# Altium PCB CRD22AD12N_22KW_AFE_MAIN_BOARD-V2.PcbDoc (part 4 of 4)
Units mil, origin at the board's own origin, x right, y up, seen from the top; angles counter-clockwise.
Board outline 14411 x 7330.3 mil, 4 copper layers (TOP, GND02, POWER03, BOTTOM), stack 78.531 mil thick; 589 components, 281 nets, 1401 pads, 282 vias.
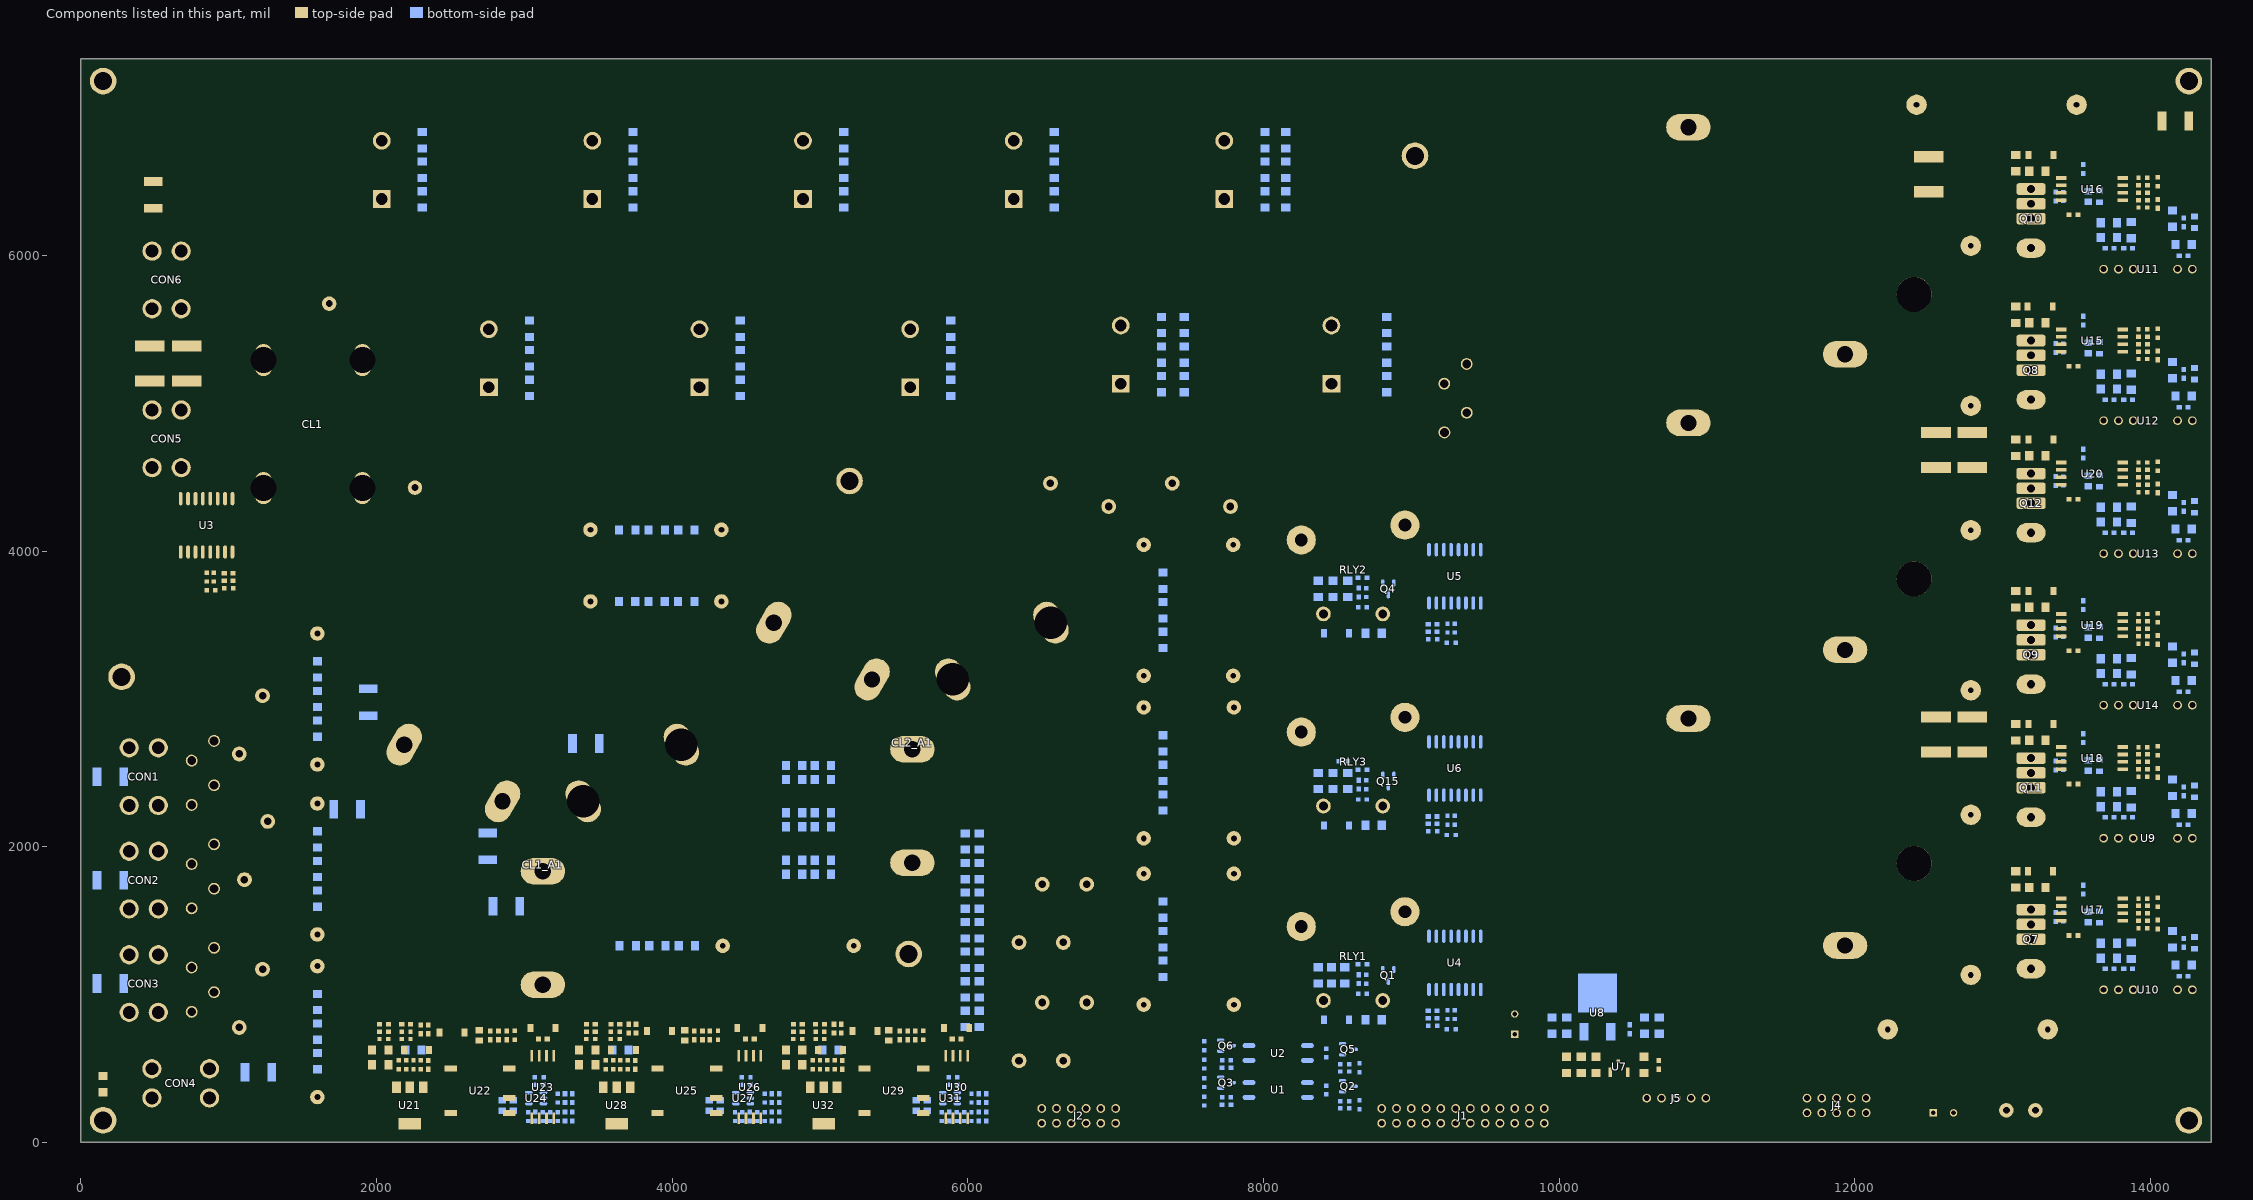
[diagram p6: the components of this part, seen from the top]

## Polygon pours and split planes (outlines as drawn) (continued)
N17916039 on POWER03 "POWER03-N17916039" (solid, pour order 101): 36 vertices, not listed, extent 9340,697.5 13460,7150

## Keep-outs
Multi-Layer:
  region: 13088.63,3180.31 13297.29,3180.31 13297.29,3219.68 13088.63,3219.68

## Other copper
TOP:
  pour cut-out: 1781.41,2300 ccw(c1950,2300) 1950,2131.41 ccw(c1950,2300) 2118.59,2300 ccw(c1950,2300) 1950,2468.59 ccw(c1950,2300)
  pour cut-out: 7061,2057.09 ccw(c7190,2057.09) 7190,1928.09 ccw(c7190,2057.09) 7319,2057.09 ccw(c7190,2057.09) 7190,2186.09 ccw(c7190,2057.09)
  pour cut-out: 5350,1275 ccw(c5600,1275) 5600,1025 ccw(c5600,1275) 5850,1275 ccw(c5600,1275) 5600,1525 ccw(c5600,1275)
  pour cut-out: 1391,2292.91 ccw(c1600,2292.91) 1600,2083.91 ccw(c1600,2292.91) 1809,2292.91 ccw(c1600,2292.91) 1600,2501.91 ccw(c1600,2292.91)
  pour cut-out: 1781.41,2200 ccw(c1950,2200) 1950,2031.41 ccw(c1950,2200) 2118.59,2200 ccw(c1950,2200) 1950,2368.59 ccw(c1950,2200)
  pour cut-out: 8775,6675 ccw(c9025,6675) 9025,6425 ccw(c9025,6675) 9275,6675 ccw(c9025,6675) 9025,6925 ccw(c9025,6675)
  pour cut-out: 4551.54,1330 4549.75,1357.34 4544.4,1384.21 4535.6,1410.15 4523.48,1434.73 4508.26,1457.51 4490.19,1478.1 4469.6,1496.17 4446.82,1511.39 4422.24,1523.51 4396.3,1532.31 4369.43,1537.66 4342.09,1539.45 4314.75,1537.66 4287.88,1532.31 4261.94,1523.51 4237.37,1511.39 4214.59,1496.17 4193.99,1478.1 4175.92,1457.51 4160.7,1434.73 4148.58,1410.15 4139.78,1384.21 4134.43,1357.34 4132.64,1330 4134.43,1302.66 4139.78,1275.79 4148.58,1249.85 4160.7,1225.27 4175.92,1202.49 4193.99,1181.9 4214.59,1163.83 4237.37,1148.61 4261.94,1136.49 4287.88,1127.69 4314.75,1122.34 4342.09,1120.55 4369.43,1122.34 4396.3,1127.69 4422.24,1136.49 4446.82,1148.61 4469.6,1163.83 4490.19,1181.9 4508.26,1202.49 4523.48,1225.27 4535.6,1249.85 4544.4,1275.79 4549.75,1302.66 4551.54,1330
  pour cut-out: 1779.48,1300 1788.13,1283.95 1795.35,1267.21 1801.08,1249.9 1805.28,1232.15 1807.92,1214.11 1808.98,1195.91 1809,1192.91 1808.21,1174.69 1805.83,1156.62 1801.88,1138.82 1796.4,1121.43 1789.42,1104.58 1781,1088.41 1771.2,1073.03 1760.1,1058.57 1747.79,1045.12 1734.34,1032.8 1719.88,1021.7 1704.5,1011.91 1688.33,1003.49 1671.48,996.51 1654.09,991.03 1636.29,987.08 1618.22,984.7 1600,983.91 1581.78,984.7 1563.71,987.08 1545.91,991.03 1528.52,996.51 1511.67,1003.49 1495.5,1011.91 1480.12,1021.7 1465.66,1032.8 1452.21,1045.12 1439.9,1058.57 1428.8,1073.03 1419,1088.41 1410.58,1104.58 1403.6,1121.43 1398.12,1138.82 1394.17,1156.62 1391.79,1174.69 1391,1192.91 1391.79,1211.12 1394.17,1229.2 1398.12,1247 1403.6,1264.39 1410.58,1281.24 1419,1297.41 1420.52,1300 1411.87,1316.05 1404.65,1332.79 1398.92,1350.1 1394.72,1367.84 1392.08,1385.88 1391.02,1404.09 1391,1407.09 1391.79,1425.3 1394.17,1443.38 1398.12,1461.18 1403.6,1478.57 1410.58,1495.42 1419,1511.59 1428.8,1526.97 1439.9,1541.43 1452.21,1554.88 1465.66,1567.19 1480.12,1578.29 1495.5,1588.09 1511.67,1596.51 1528.52,1603.49 1545.91,1608.97 1563.71,1612.92 1581.78,1615.3 1600,1616.09 1618.22,1615.3 1636.29,1612.92 1654.09,1608.97 1671.48,1603.49 1688.33,1596.51 1704.5,1588.09 1719.88,1578.29 1734.34,1567.19 1747.79,1554.88 1760.1,1541.43 1771.2,1526.97 1781,1511.59 1789.42,1495.42 1796.4,1478.57 1801.88,1461.18 1805.83,1443.38 1808.21,1425.3 1809,1407.09 1808.21,1388.87 1805.83,1370.8 1801.88,1353 1796.4,1335.61 1789.42,1318.76 1781,1302.59 1779.48,1300
  pour cut-out: 5700.48,1275 5698.55,1294.6 5692.84,1313.45 5683.55,1330.83 5671.05,1346.05 5655.83,1358.55 5638.45,1367.83 5619.6,1373.55 5600,1375.48 5580.4,1373.55 5561.54,1367.83 5549.97,1361.65 5544.17,1358.55 5528.94,1346.05 5516.45,1330.83 5507.16,1313.45 5501.44,1294.6 5499.51,1275 5501.44,1255.39 5507.16,1236.54 5516.45,1219.17 5528.94,1203.94 5544.17,1191.45 5549.97,1188.35 5561.54,1182.16 5580.4,1176.44 5600,1174.51 5619.6,1176.44 5638.45,1182.16 5655.83,1191.45 5671.05,1203.94 5683.55,1219.17 5692.84,1236.54 5698.55,1255.39 5700.48,1275
  pour cut-out: 14324.09,5908.07 14322.74,5918.38 14318.76,5927.99 14312.42,5936.24 14304.17,5942.57 14294.56,5946.55 14284.25,5947.91 14273.94,5946.55 14264.33,5942.57 14256.08,5936.24 14249.74,5927.99 14245.76,5918.38 14244.41,5908.07 14245.76,5897.76 14249.74,5888.15 14256.08,5879.9 14264.33,5873.56 14273.94,5869.58 14284.25,5868.23 14294.56,5869.58 14304.17,5873.56 14312.42,5879.9 14318.76,5888.15 14322.74,5897.76 14324.09,5908.07
  pour cut-out: 14324.09,4883.07 14322.74,4893.38 14318.76,4902.99 14312.42,4911.24 14304.17,4917.57 14294.56,4921.55 14284.25,4922.91 14273.94,4921.55 14264.33,4917.57 14256.08,4911.24 14249.74,4902.99 14245.76,4893.38 14244.41,4883.07 14245.76,4872.76 14249.74,4863.15 14256.08,4854.9 14264.33,4848.56 14273.94,4844.58 14284.25,4843.23 14294.56,4844.58 14304.17,4848.56 14312.42,4854.9 14318.76,4863.15 14322.74,4872.76 14324.09,4883.07
  pour cut-out: 14324.09,3983.07 14322.74,3993.38 14318.76,4002.99 14312.42,4011.24 14304.17,4017.57 14294.56,4021.55 14284.25,4022.91 14273.94,4021.55 14264.33,4017.57 14256.08,4011.24 14249.74,4002.99 14245.76,3993.38 14244.41,3983.07 14245.76,3972.76 14249.74,3963.15 14256.08,3954.9 14264.33,3948.56 14273.94,3944.58 14284.25,3943.23 14294.56,3944.58 14304.17,3948.56 14312.42,3954.9 14318.76,3963.15 14322.74,3972.76 14324.09,3983.07
  pour cut-out: 14324.09,2958.07 14322.74,2968.38 14318.76,2977.99 14312.42,2986.24 14304.17,2992.57 14294.56,2996.55 14284.25,2997.91 14273.94,2996.55 14264.33,2992.57 14256.08,2986.24 14249.74,2977.99 14245.76,2968.38 14244.41,2958.07 14245.76,2947.76 14249.74,2938.15 14256.08,2929.9 14264.33,2923.56 14273.94,2919.58 14284.25,2918.23 14294.56,2919.58 14304.17,2923.56 14312.42,2929.9 14318.76,2938.15 14322.74,2947.76 14324.09,2958.07
  pour cut-out: 14324.09,2058.07 14322.74,2068.38 14318.76,2077.99 14312.42,2086.24 14304.17,2092.57 14294.56,2096.55 14284.25,2097.91 14273.94,2096.55 14264.33,2092.57 14256.08,2086.24 14249.74,2077.99 14245.76,2068.38 14244.41,2058.07 14245.76,2047.76 14249.74,2038.15 14256.08,2029.9 14264.33,2023.56 14273.94,2019.58 14284.25,2018.23 14294.56,2019.58 14304.17,2023.56 14312.42,2029.9 14318.76,2038.15 14322.74,2047.76 14324.09,2058.07
  pour cut-out: 10632.95,300 10631.6,310.31 10627.62,319.92 10621.28,328.17 10613.03,334.5 10603.42,338.49 10593.11,339.84 10582.8,338.49 10573.19,334.5 10564.94,328.17 10558.6,319.92 10554.62,310.31 10553.27,300 10554.62,289.69 10558.6,280.08 10564.94,271.83 10573.19,265.5 10582.8,261.51 10593.11,260.16 10603.42,261.51 10613.03,265.5 10621.28,271.83 10627.62,280.08 10631.6,289.69 10632.95,300
  pour cut-out: 7249.29,2057.09 7248.15,2068.66 7244.77,2079.78 7239.3,2090.03 7231.92,2099.01 7222.94,2106.39 7212.69,2111.87 7201.57,2115.24 7190,2116.38 7178.43,2115.24 7167.31,2111.87 7160.48,2108.22 7157.06,2106.39 7148.08,2099.01 7140.7,2090.03 7135.23,2079.78 7131.85,2068.66 7130.71,2057.09 7131.85,2045.52 7135.23,2034.4 7140.7,2024.15 7148.08,2015.17 7157.06,2007.8 7160.48,2005.97 7167.31,2002.32 7178.43,1998.94 7190,1997.8 7201.57,1998.94 7212.69,2002.32 7222.94,2007.8 7231.92,2015.17 7239.3,2024.15 7244.77,2034.4 7248.15,2045.52 7249.29,2057.09
  pour cut-out: 10935,6617.72 10815,6617.72 10793.21,6618.67 10771.59,6621.51 10750.29,6626.23 10729.49,6632.79 10709.34,6641.14 10690,6651.21 10671.6,6662.93 10654.3,6676.2 10638.22,6690.94 10623.49,6707.02 10610.21,6724.32 10598.49,6742.72 10588.42,6762.06 10580.08,6782.21 10573.52,6803.01 10568.8,6824.3 10565.95,6845.93 10565,6867.72 10565.95,6889.51 10568.8,6911.13 10573.52,6932.42 10580.08,6953.22 10588.42,6973.37 10598.49,6992.72 10610.21,7011.11 10623.49,7028.42 10638.22,7044.5 10654.3,7059.23 10671.6,7072.51 10690,7084.23 10709.34,7094.3 10729.49,7102.64 10750.29,7109.2 10771.59,7113.92 10793.21,7116.77 10815,7117.72 10935,7117.72 10956.79,7116.77 10978.41,7113.92 10999.71,7109.2 11020.51,7102.64 11040.66,7094.3 11060,7084.23 11078.4,7072.51 11095.7,7059.23 11111.78,7044.5 11126.51,7028.42 11139.79,7011.11 11151.51,6992.72 11161.58,6973.37 11169.92,6953.22 11176.48,6932.42 11181.2,6911.13 11184.05,6889.51 11185,6867.72 11184.05,6845.93 11181.2,6824.3 11176.48,6803.01 11169.92,6782.21 11161.58,6762.06 11151.51,6742.72 11139.79,6724.32 11126.51,6707.02 11111.78,6690.94 11095.7,6676.2 11078.4,6662.93 11060,6651.21 11040.66,6641.14 11020.51,6632.79 10999.71,6626.23 10978.41,6621.51 10956.79,6618.67 10935,6617.72
GND02:
  drawing of 114 lines, arcs and shapes, not listed
POWER03:
  drawing of 52 lines, arcs and shapes, not listed
BOTTOM:
  region net N17927817: 14240,1010 14240,1155 14255,1170 14255,1260 14275,1280 14275,1320 14285,1330 14345,1330 14350,1325 14350,1010 14340,1000 14250,1000 14240,1010
  region net PFC_G_HC: 13910,3260 13905,3255 13835,3255 13825,3245 13825,3130 13835,3120 13835,2940 13825,2930 13755,2930 13740,2945 13740,3118 13750,3128 13750,3310 13755,3315 13905,3315 13910,3310 13910,3260
  region net N17922803: 13550.34,5430 13480.34,5500 13480.34,5540 13490.34,5550 13515.34,5550 13575.34,5550 13640.34,5550 13680.34,5510 13680.34,5400 13675.34,5395 13560.34,5395 13550.34,5405 13550.34,5430
  region net -3V_PFCHA: 13855,1010 13855,1150 13865,1160 13865,1200 13845,1220 13845,1265 13850,1270 13915,1270 13925,1260 13925,1010 13915,1000 13865,1000 13855,1010
  region net N17924549: 13550.34,2605 13480.34,2675 13480.34,2715 13490.34,2725 13515.34,2725 13575.34,2725 13640.34,2725 13680.34,2685 13680.34,2575 13675.34,2570 13560.34,2570 13550.34,2580 13550.34,2605
  region net N17898311: 1646,2079 1645,2080 1540,2080 1525,2095 1525,2335 1535,2345 1645,2345 1675,2315 1725,2315 1735,2305 1738,2305 1738,2171 1646,2079
  region net N17951662: 9105,1085 9175,1085 9180,1080 9180,985 9175,980 9100,980 9095,985 9095,1075 9105,1085
  region net VP+15V_PFCHB: 13640,4845 13630,4855 13630,5235 13630,5250 13630,5350 13635,5355 13685,5355 13695,5345 13695,5235 13695,5225 13695,5063 13715,5043 13715,4850 13710,4845 13640,4845
  region net VP+15V: 14230,3290 14255,3290 14260,3295 14335,3295 14345,3295 14350,3300 14350,3400 14345,3405 14335,3405 14130,3405 14120,3405 14110,3395 14110,3330 14115,3325 14185,3325 14220,3290 14230,3290
  region net GND_EARTH: 2810,1525 2730,1525 2725,1530 2725,1660 2730,1665 2810,1665 2815,1660 2815,1530 2810,1525
  region net GGND: 14200,4845 14110,4845 14105,4845 14095,4855 14095,4860 14095,5185 14100,5190 14235,5190 14240,5185 14240,5135 14210,5105 14195,5090 14195,5020 14210,5005 14210,4855 14200,4845
  region net PFC_G_LC: 13910,4285 13905,4280 13835,4280 13825,4270 13825,4155 13835,4145 13835,3965 13825,3955 13755,3955 13740,3970 13740,4143 13750,4153 13750,4335 13755,4340 13900,4340 13910,4330 13910,4285
  region net VP+15V: 14230,1365 14255,1365 14260,1370 14335,1370 14345,1370 14350,1375 14350,1475 14345,1480 14335,1480 14130,1480 14120,1480 14110,1470 14110,1405 14115,1400 14185,1400 14220,1365 14230,1365
  region net GGND: 14200,3945 14110,3945 14105,3945 14095,3955 14095,3960 14095,4285 14100,4290 14235,4290 14240,4285 14240,4235 14210,4205 14195,4190 14195,4110 14210,4095 14210,3955 14200,3945
  region net VP+15V_PFCLB: 13640,5870 13630,5880 13630,6260 13630,6275 13630,6370 13640,6380 13680,6380 13690,6380 13695,6375 13695,6365 13695,6260 13695,6250 13695,6088 13715,6068 13715,5875 13710,5870 13640,5870
  region net N17928860: 14240,4860 14240,5005 14255,5020 14255,5110 14275,5130 14275,5170 14285,5180 14345,5180 14350,5175 14350,4860 14340,4850 14250,4850 14240,4860
  region net VP+15V_PFCLA: 13640,2020 13630,2030 13630,2410 13630,2425 13630,2520 13640,2530 13685,2530 13695,2520 13695,2410 13695,2400 13695,2238 13715,2218 13715,2025 13710,2020 13640,2020
  region net GND_EARTH: 1860,2180 1860,2320 1865,2325 1955,2325 1965,2315 1965,2185 1955,2175 1865,2175 1860,2180
  pour cut-out: 12704.21,200 12703,209.14 12699.48,217.65 12693.87,224.96 12686.55,230.57 12678.04,234.1 12668.9,235.3 12659.76,234.1 12651.25,230.57 12643.94,224.96 12638.33,217.65 12634.8,209.14 12633.6,200 12634.8,190.86 12638.33,182.35 12643.94,175.04 12651.25,169.43 12659.76,165.9 12668.9,164.7 12678.04,165.9 12686.55,169.43 12693.87,175.04 12699.48,182.35 12703,190.86 12704.21,200
  pour cut-out: 13085.07,217.71 13083.93,229.28 13080.56,240.4 13075.08,250.65 13067.7,259.64 13058.72,267.01 13048.47,272.49 13037.35,275.86 13025.78,277 13014.21,275.86 13003.09,272.49 12996.26,268.84 12992.84,267.01 12983.86,259.64 12976.49,250.65 12971.01,240.4 12967.63,229.28 12966.49,217.71 12967.63,206.15 12971.01,195.03 12976.49,184.78 12983.86,175.79 12992.84,168.42 12996.26,166.59 13003.09,162.94 13014.21,159.57 13025.78,158.43 13037.35,159.57 13048.47,162.94 13058.72,168.42 13067.7,175.79 13075.08,184.78 13080.56,195.03 13083.93,206.15 13085.07,217.71
  region net VP+15V: 14230,5215 14255,5215 14260,5220 14335,5220 14345,5220 14350,5225 14350,5325 14345,5330 14335,5330 14130,5330 14120,5330 14110,5320 14110,5255 14115,5250 14185,5250 14220,5215 14230,5215
  region net -3V_PFCLB: 13855,5885 13855,6025 13865,6035 13865,6075 13845,6095 13845,6140 13850,6145 13915,6145 13925,6135 13925,5885 13915,5875 13865,5875 13855,5885
  region net GGND: 14200,5870 14110,5870 14105,5870 14095,5880 14095,5885 14095,6210 14100,6215 14235,6215 14240,6210 14240,6160 14210,6130 14195,6115 14195,6045 14210,6030 14210,5880 14200,5870
  region net VP+15V_PFCHC: 13640,2920 13630,2930 13630,3310 13630,3325 13630,3425 13635,3430 13680,3430 13690,3430 13695,3425 13695,3415 13695,3367 13695,3310 13695,3300 13695,3138 13715,3118 13715,2925 13710,2920 13640,2920
  region net -3V_PFCLC: 13855,3960 13855,4100 13865,4110 13865,4150 13845,4170 13845,4215 13850,4220 13920,4220 13925,4215 13925,3960 13915,3950 13865,3950 13855,3960
  region net N17930400: 14240,3960 14240,4095 14255,4110 14255,4210 14275,4230 14275,4270 14285,4280 14345,4280 14350,4275 14350,3960 14340,3950 14250,3950 14240,3960
  region net N17751858: 13550.34,1580 13480.34,1650 13480.34,1690 13490.34,1700 13515.34,1700 13575.34,1700 13640.34,1700 13680.34,1660 13680.34,1550 13675.34,1545 13560.34,1545 13550.34,1555 13550.34,1580
  pour cut-out: 9839.84,230 9838.49,240.31 9834.51,249.92 9828.17,258.17 9819.92,264.5 9810.31,268.49 9800,269.84 9789.69,268.49 9780.08,264.5 9771.83,258.17 9765.49,249.92 9761.51,240.31 9760.16,230 9761.51,219.69 9765.49,210.08 9771.83,201.83 9780.08,195.5 9789.69,191.51 9800,190.16 9810.31,191.51 9819.92,195.5 9828.17,201.83 9834.51,210.08 9838.49,219.69 9839.84,230
  pour cut-out: 9939.84,230 9938.49,240.31 9934.51,249.92 9928.17,258.17 9919.92,264.5 9910.31,268.49 9900,269.84 9889.69,268.49 9880.08,264.5 9871.83,258.17 9865.49,249.92 9861.51,240.31 9860.16,230 9861.51,219.69 9865.49,210.08 9871.83,201.83 9880.08,195.5 9889.69,191.51 9900,190.16 9910.31,191.51 9919.92,195.5 9928.17,201.83 9934.51,210.08 9938.49,219.69 9939.84,230
  region net GGND: 14200,2020 14110,2020 14105,2020 14095,2030 14095,2035 14095,2360 14100,2365 14235,2365 14240,2360 14240,2310 14210,2280 14195,2265 14195,2190 14210,2175 14210,2030 14200,2020
  region net N17930170: 14240,2935 14240,3065 14255,3080 14255,3185 14275,3205 14275,3245 14285,3255 14345,3255 14350,3250 14350,2935 14340,2925 14250,2925 14240,2935
  region net PFC_G_HB: 13910,5185 13905,5180 13835,5180 13825,5170 13825,5055 13835,5045 13835,4865 13825,4855 13755,4855 13740,4870 13740,5043 13750,5053 13750,5235 13755,5240 13905,5240 13910,5235 13910,5185
  region net N17953229: 9105,2400 9175,2400 9180,2395 9180,2300 9175,2295 9100,2295 9095,2300 9095,2390 9105,2400
  region net -3V_PFCHB: 13855,4860 13855,5000 13865,5010 13865,5050 13845,5070 13845,5115 13850,5120 13915,5120 13925,5110 13925,4860 13915,4850 13865,4850 13855,4860
  region net VP+15V: 14230,4315 14255,4315 14260,4320 14335,4320 14345,4320 14350,4325 14350,4425 14345,4430 14335,4430 14130,4430 14120,4430 14110,4420 14110,4355 14115,4350 14185,4350 14220,4315 14230,4315
  region net N18031698: 1312.5,4300 1160,4300 1115,4345 1115,4540 1160,4585 1300,4585 1352.5,4532.5 1352.5,4340 1312.5,4300
  region net N17925612: 13550.34,4530 13480.34,4600 13480.34,4640 13490.34,4650 13515.34,4650 13575.34,4650 13640.34,4650 13680.34,4610 13680.34,4500 13675.34,4495 13560.34,4495 13550.34,4505 13550.34,4530
  region net GGND: 14200,2920 14110,2920 14105,2920 14095,2930 14095,2935 14095,3260 14100,3265 14235,3265 14240,3260 14240,3215 14200,3175 14200,3085 14210,3075 14210,2930 14200,2920
  region net GND_EARTH: 2010,3035 1880,3035 1875,3040 1875,3130 1885,3140 2010,3140 2020,3130 2020,3045 2010,3035
  region net GGND: 14200,995 14110,995 14105,995 14095,1005 14095,1010 14095,1335 14100,1340 14235,1340 14240,1335 14240,1285 14210,1255 14195,1240 14195,1170 14210,1155 14210,1005 14200,995
  region net -3V_PFCHC: 13855,2935 13855,3075 13865,3085 13865,3125 13845,3145 13845,3190 13850,3195 13920,3195 13925,3190 13925,2935 13915,2925 13865,2925 13855,2935
  region net N17453218: 14240,2035 14240,2180 14255,2195 14255,2280 14255,2285 14275,2305 14275,2345 14285,2355 14345,2355 14350,2350 14350,2035 14340,2025 14250,2025 14240,2035
  region net PFC_G_LA: 13910,2360 13905,2355 13835,2355 13825,2345 13825,2230 13835,2220 13835,2040 13825,2030 13755,2030 13740,2045 13740,2218 13750,2228 13750,2410 13755,2415 13905,2415 13910,2410 13910,2360
  region net N17952680: 9105,3700 9175,3700 9180,3695 9180,3600 9175,3595 9100,3595 9095,3600 9095,3690 9105,3700
  region net GND_EARTH: 2695,1940 2810,1940 2815,1935 2815,1850 2800,1835 2695,1835 2685,1845 2685,1930 2695,1940
  region net PFC_G_HA: 13910,1335 13905,1330 13835,1330 13825,1320 13825,1205 13835,1195 13835,1015 13825,1005 13755,1005 13740,1020 13740,1193 13750,1203 13750,1385 13755,1390 13905,1390 13910,1385 13910,1335
  region net N17925397: 13550.34,3505 13480.34,3575 13480.34,3615 13490.34,3625 13515.34,3625 13575.34,3625 13640.34,3625 13680.34,3585 13680.34,3475 13675.34,3470 13560.34,3470 13550.34,3480 13550.34,3505
  region net -3V_PFCLA: 13855,2035 13855,2175 13865,2185 13865,2225 13845,2245 13845,2290 13850,2295 13920,2295 13925,2290 13925,2035 13915,2025 13865,2025 13855,2035
  region net VP+15V: 14230,6240 14255,6240 14260,6245 14335,6245 14345,6245 14350,6250 14350,6350 14345,6355 14335,6355 14130,6355 14120,6355 14110,6345 14110,6280 14115,6275 14185,6275 14220,6240 14230,6240
  region net PFC_G_LB: 13910,6210 13905,6205 13835,6205 13825,6195 13825,6080 13835,6070 13835,5890 13825,5880 13755,5880 13740,5895 13740,6068 13750,6078 13750,6260 13755,6265 13905,6265 13910,6260 13910,6210
  region net VP+15V_PFCLC: 13640,3945 13630,3955 13630,4335 13630,4350 13630,4445 13640,4455 13685,4455 13695,4445 13695,4335 13695,4325 13695,4163 13715,4143 13715,3950 13710,3945 13640,3945
  region net N17929090: 14240,5885 14240,6030 14255,6045 14255,6135 14275,6155 14275,6195 14285,6205 14345,6205 14350,6200 14350,5885 14340,5875 14250,5875 14240,5885
  region net VP+15V: 14230,2390 14255,2390 14260,2395 14335,2395 14345,2395 14350,2400 14350,2500 14345,2505 14335,2505 14130,2505 14120,2505 14110,2495 14110,2430 14115,2425 14185,2425 14220,2390 14230,2390
  region net N17923421: 13550.34,6455 13480.34,6525 13480.34,6565 13490.34,6575 13515.34,6575 13575.34,6575 13640.34,6575 13680.34,6535 13680.34,6425 13675.34,6420 13560.34,6420 13550.34,6430 13550.34,6455
  region net VP+15V_PFCHA: 13640,995 13630,1005 13630,1385 13630,1400 13630,1495 13640,1505 13685,1505 13695,1495 13695,1385 13695,1375 13695,1213 13715,1193 13715,1000 13710,995 13640,995

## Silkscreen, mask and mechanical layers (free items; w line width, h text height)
Top Overlay:
  drawing of 2027 lines, arcs and shapes, not listed
  text "CRD22AD12N_22KW_MAIN_BOARD" at 1799,4062.83 h35
  text "Rev B 1820" at 1799,3956 h35
Bottom Solder:
  region: 9080,4110 9090,4100 9205,4100 9220,4115 9220,4250 9205,4265 9095,4265 9080,4250
  region: 9085,2800 9095,2790 9210,2790 9225,2805 9225,2940 9210,2955 9100,2955 9085,2940
  region: 9075,1510 9085,1500 9200,1500 9215,1515 9215,1650 9200,1665 9090,1665 9075,1650
  region: 9390,1540 9430,1500 9949.29,1500 10257.14,1807.86 10979.64,2530.36 11065,2615.71 11065,2705 11025,2745 10430,2745 10365,2680 9585,1900 9390,1705
  region: 9392.86,2822.14 9425,2790 9985,2790 10145,2950 11290,4095 11290,4690 11250,4730 10855,4730 10805,4680 10805,4490 10550,4235 10550,4234.29 9392.86,3077.14
  region: 9340,4110 9340,4315 9925,4900 9925,6054.29 9925.36,6054.64 10608.21,6737.5 11125,6737.5 11180,6682.5 11180,6405.71 11070,6295.71 10462.16,5687.87 10462.16,4542.16 10030,4110
  lines w0.5: 9075,1510 9075,1650 9090,1665 9200,1665 9215,1650 9215,1515 9200,1500 9085,1500 9075,1510 ; 9080,4110 9080,4250 9095,4265 9205,4265 9220,4250 9220,4115 9205,4100 9090,4100 9080,4110 ; 9085,2800 9085,2940 9100,2955 9210,2955 9225,2940 9225,2805 9210,2790 9095,2790 9085,2800 ; 9340,4110 9340,4315 9925,4900 9925,6054.29 9925.36,6054.64 10608.21,6737.5 10671.79,6737.5 11125,6737.5 11180,6682.5 11180,6405.71 11070,6295.71 10462.16,5687.87 10462.16,4542.16 10030,4110 9925,4110 9340,4110 ; 9390,1540 9390,1705 9585,1900 10365,2680 10430,2745 11025,2745 11065,2705 11065,2615.71 10979.64,2530.36 10257.14,1807.86 9949.29,1500 9430,1500 9390,1540 ; 9392.86,2822.14 9392.86,2970 9392.86,3077.14 10550,4234.29 10550,4235 10805,4490 10805,4680 10855,4730 11250,4730 11290,4690 11290,4540 11290,4095 10145,2950 9985,2790 9425,2790 9392.86,2822.14
DESIGN_OUTLINE:
  the board outline again, w1
Mechanical 255:
  lines w1: 9075,50 9200,50 9200,200 9075,200 9075,50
